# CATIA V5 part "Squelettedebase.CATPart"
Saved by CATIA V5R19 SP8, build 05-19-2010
Part number: Squelettedebase
Publications: "Hauteursaxesbati", "EntraxeAB", "entraxeDoigtAC"
Bounding box of the stored display mesh (mm): x 0 to 0, y 46 to 100, z 60 to 60
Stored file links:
  C:\Users\rcousturie\Desktop\EU_thinkMotion\iao\IAO_MMS_Groupe1\abergami\abergami_catiaInitial\ObjetsInitials\Squelettedebase.CATPart
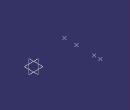
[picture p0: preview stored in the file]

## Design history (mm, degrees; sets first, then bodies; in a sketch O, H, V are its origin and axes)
Parameters
  Hauteursaxesbati = 60 mm
  EntraxeAB = 9 mm
  entraxeDoigtAC = 36 mm
  largeurrainure = 18 mm
Set1
  Point1: (0, 100, 60 {= Hauteursaxesbati})
  Point2: (0, 91 {= 100mm-EntraxeAB}, 60 {= Hauteursaxesbati})
  Point3: (0, 64 {= 100mm-entraxeDoigtAC}, 60 {= Hauteursaxesbati})
  Point4: (0, 46 {= 100mm-entraxeDoigtAC -largeurrainure}, 60 {= Hauteursaxesbati})
Body1 (main body)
